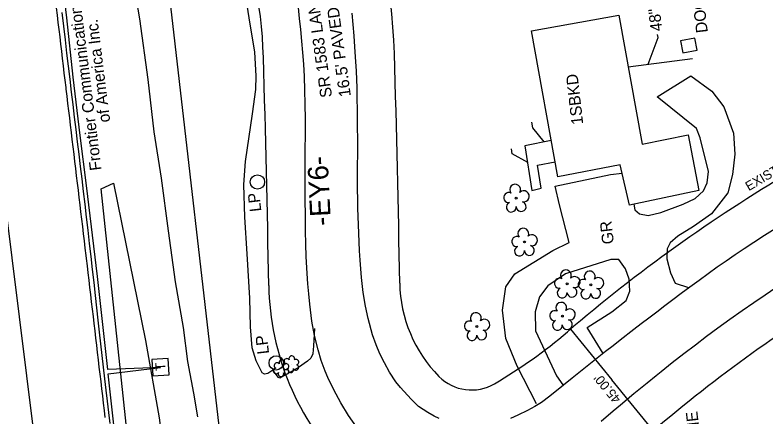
# Model space of a CAD drawing. Extents: x 472260 to 482161, y 489063 to 507124.
# Drawn here: x 478120.1 to 478378, y 497381.3 to 497519.2 of the extents above; entities that cross this region are included whole.
import ezdxf

# ---------------------------------------------------------------- set-up
doc = ezdxf.new("R2010")
doc.units = 0
for name, color, linetype in [('Exist Plan Preparation Watershed Blue', 7, 'Continuous'), ('Exist Structure Minor Drop Inlet Cogo Elevation', 7, 'Continuous'), ('Exist Structure Minor Pipes CMP 15 Inch Cogo Comment', 7, 'Continuous'), ('Exist Structure Minor Pipes CMP 15 Inch Cogo Point CELL', 7, 'Continuous'), ('Prop Drainage Structure Catch Basin Convert From Junction Box Label', 7, 'Continuous'), ('Prop Drainage Structure Drop Inlet Grate 2 Narrow Slots and Sag Grates 840 24 CELL', 7, 'Continuous'), ('Prop Drainage Structure Drop Inlet Grate 2 Narrow Slots and Sag Grates 840 24 Label', 7, 'Continuous'), ('Prop Drainage Structure Drop Inlet Grate 2 Wide Slots and Flat Grates 840 20 Label', 7, 'Continuous'), ('Prop Drainage Structure Drop Inlet Grate 2 Wide Slots and Sag Grates 840 22 Label', 7, 'Continuous'), ('Prop Drainage Structure Outlet Berm Ditch 850 10 CELL', 7, 'Continuous'), ('Prop Drainage Structure Outlet Berm Ditch 850 10 Label', 7, 'Continuous'), ('Prop Drainage Structure Pipe Collar CELL', 7, 'Continuous'), ('Prop Drainage Structure Pipe Collar Label', 7, 'Continuous'), ('Prop Drainage Structure Pipe RCP 18in Class III', 7, 'Continuous'), ('Prop Drainage Structure Pipe RCP 66in Class III Label', 7, 'Continuous'), ('Prop Drainage Structure Pipe RCP 72in Class III', 7, 'Continuous'), ('Prop Drainage Structure Pipe Stub Out CELL', 7, 'Continuous'), ('Prop Drainage Structure Pipe Welded Steel 42in', 7, 'Continuous'), ('Prop Drainage Structure Tops and Inverts LABEL', 7, 'Continuous'), ('Prop Earthen Structure Ditch Flow Line', 7, 'Continuous'), ('Prop Earthen Structure False Sump Label', 7, 'Continuous'), ('Prop Erosion Rip Rap Class B', 7, 'Continuous'), ('Prop Erosion Rip Rap Pad at Outlet CELL', 7, 'Continuous'), ('Prop SS Fill Line', 7, 'Continuous'), ('Scratch_Level_4', 7, 'Continuous')]:
    doc.layers.add(name, color=color, linetype=linetype)

msp = doc.modelspace()

# ---------------------------------------------------------------- linework, layer by layer
at = {"layer": 'Exist Plan Preparation Watershed Blue'}
msp.add_lwpolyline([(478304.26, 497476.19), (478295.26, 497474.27), (478297.62, 497459.04), (478300.85, 497459.8), (478299.55, 497467.66), (478305.58, 497468.87)], dxfattribs=at)
at = {"layer": 'Exist Structure Minor Drop Inlet Cogo Elevation'}
msp.add_line((478344.04, 496042.24), (478169.39, 497559.09), dxfattribs=at)
for centre, radius, start, end in [((478049.09, 497499.96), 201.41, 1.7193, 42.703), ((478049.09, 497499.96), 156.41, 1.7193, 42.7417), ((472276.25, 497326.67), 5976.85, 0.96365, 1.719327), ((472276.25, 497326.67), 5931.85, 0.96365, 1.719327), ((478660.76, 497000.88), 539.39, 120.545, 130.5894), ((478298.83, 497427.98), 91.59, 180.9636, 224.7163), ((478298.83, 497427.98), 46.59, 180.9636, 224.7163), ((478660.76, 497000.88), 494.39, 120.545, 130.5894), ((478198.36, 497540.58), 171.31, 300.3104, 310.5894), ((478276.89, 497406.25), 15.71, 224.7163, 300.3104)]:
    msp.add_arc(centre, radius, start, end, dxfattribs=at)
at = {"layer": 'Exist Structure Minor Pipes CMP 15 Inch Cogo Comment'}
for p in [(478310.9, 497411.38), (478339.39, 497376.55)]:
    msp.add_line(p, (478325.14, 497393.97), dxfattribs=at)
at = {"layer": 'Prop Drainage Structure Catch Basin Convert From Junction Box Label'}
for p, q in [((478128.54, 497360.08), (478111.35, 497498.02)), ((478170.09, 497398.3), (478151.97, 497397.59)), ((478152.13, 497396.04), (478170.09, 497398.3))]:
    msp.add_line(p, q, dxfattribs=at)
for points in [[(478151.97, 497397.59), (478151.77, 497399.63), (478148.48, 497429.53), (478144.63, 497460.75), (478142.47, 497477.82), (478140.06, 497497.85), (478137.95, 497518.18), (478136.03, 497533.62), (478133.37, 497557.17), (478129.16, 497589.17), (478126.48, 497613.21), (478115.94, 497710.98)], [(478163.86, 497293.38), (478161.83, 497310.95), (478158.51, 497339.17), (478155.33, 497367.28), (478152.13, 497396.04)]]:
    msp.add_lwpolyline(points, dxfattribs=at)
at = {"layer": 'Prop Drainage Structure Drop Inlet Grate 2 Narrow Slots and Sag Grates 840 24 CELL'}
msp.add_lwpolyline([(478134.27, 497521.64), (478134.57, 497519.16), (478134.87, 497516.68), (478135.16, 497514.19), (478135.46, 497511.71), (478135.75, 497509.23), (478136.05, 497506.75), (478136.34, 497504.26), (478136.64, 497501.78), (478136.94, 497499.3), (478137.23, 497496.82), (478137.53, 497494.33), (478137.59, 497493.8), (478137.89, 497491.32), (478138.19, 497488.84), (478138.49, 497486.36), (478138.78, 497483.88), (478139.08, 497481.39), (478139.38, 497478.91), (478139.68, 497476.43), (478139.98, 497473.95), (478140.27, 497471.46), (478140.57, 497468.98), (478140.87, 497466.5), (478141.17, 497464.02), (478141.47, 497461.54), (478141.77, 497459.05), (478142.06, 497456.57), (478142.36, 497454.09), (478142.66, 497451.61), (478142.96, 497449.13), (478143.26, 497446.64), (478143.56, 497444.16), (478143.85, 497441.68), (478144.15, 497439.2), (478144.45, 497436.72), (478144.58, 497435.66), (478144.87, 497433.18), (478145.16, 497430.7), (478145.45, 497428.21), (478145.75, 497425.73), (478146.04, 497423.25), (478146.33, 497420.76), (478146.62, 497418.28), (478146.91, 497415.8), (478147.2, 497413.32), (478147.5, 497410.83), (478147.79, 497408.35), (478148.08, 497405.87), (478148.37, 497403.38), (478148.66, 497400.9), (478148.96, 497398.42), (478149.25, 497395.94), (478149.54, 497393.45), (478149.83, 497390.97), (478150.12, 497388.49), (478150.41, 497386), (478150.71, 497383.52), (478151, 497381.04)], dxfattribs=at)
at = {"layer": 'Prop Drainage Structure Drop Inlet Grate 2 Narrow Slots and Sag Grates 840 24 Label'}
msp.add_lwpolyline([(478337.62, 497502.34), (478340.95, 497511.46), (478340.81, 497512.52)], dxfattribs=at)
at = {"layer": 'Prop Drainage Structure Drop Inlet Grate 2 Wide Slots and Flat Grates 840 20 Label'}
for p, q in [((478292.27, 497456.39), (478292.27, 497456.39)), ((478295.08, 497441.32), (478295.08, 497441.32)), ((478309.72, 497426.98), (478309.72, 497426.98)), ((478317.87, 497426.62), (478317.87, 497426.62)), ((478308.1, 497415.88), (478308.1, 497415.88)), ((478278.75, 497412.34), (478278.75, 497412.34))]:
    msp.add_line(p, q, dxfattribs=at)
for centre in [(478292.27, 497456.39), (478295.08, 497441.32), (478309.72, 497426.98), (478317.87, 497426.62), (478308.1, 497415.88), (478278.75, 497412.34)]:
    msp.add_circle(centre, 0.326, dxfattribs=at)
for centre, radius, start, end in [((478291.89, 497459.26), 1.86, 330.1651, 219.7134), ((478294.82, 497456.98), 1.9, 257.1011, 134.1999), ((478289.67, 497456.54), 1.73, 62.6636, 279.3457), ((478290.57, 497453.27), 1.69, 111.5671, 6.231), ((478293.94, 497453.49), 1.7, 181.2822, 74.56), ((478294.69, 497444.19), 1.86, 330.1651, 219.7134), ((478297.63, 497441.91), 1.9, 257.1011, 134.1999), ((478292.47, 497441.47), 1.73, 62.6636, 279.3457), ((478293.37, 497438.2), 1.69, 111.5671, 6.231), ((478296.75, 497438.42), 1.7, 181.2822, 74.56), ((478309.34, 497429.86), 1.86, 330.1651, 219.7134), ((478317.49, 497429.49), 1.86, 330.1651, 219.7134), ((478307.12, 497427.14), 1.73, 62.6636, 279.3457), ((478312.27, 497427.57), 1.9, 257.1011, 134.1999), ((478315.27, 497426.77), 1.73, 62.6636, 279.3457), ((478320.42, 497427.21), 1.9, 257.1011, 134.1999), ((478308.02, 497423.86), 1.69, 111.5671, 6.231), ((478311.39, 497424.08), 1.7, 181.2822, 74.56), ((478319.54, 497423.72), 1.7, 181.2822, 74.56), ((478316.17, 497423.5), 1.69, 111.5671, 6.231), ((478307.72, 497418.75), 1.86, 330.1651, 219.7134), ((478305.49, 497416.03), 1.73, 62.6636, 279.3457), ((478310.65, 497416.47), 1.9, 257.1011, 134.1999), ((478278.37, 497415.21), 1.86, 330.1651, 219.7134), ((478276.15, 497412.49), 1.73, 62.6636, 279.3457), ((478281.3, 497412.93), 1.9, 257.1011, 134.1999), ((478306.4, 497412.76), 1.69, 111.5671, 6.231), ((478309.77, 497412.98), 1.7, 181.2822, 74.56), ((478277.05, 497409.22), 1.69, 111.5671, 6.231), ((478280.42, 497409.44), 1.7, 181.2822, 74.56)]:
    msp.add_arc(centre, radius, start, end, dxfattribs=at)
at = {"layer": 'Prop Drainage Structure Pipe Collar Label'}
for centre in [(478203.37, 497461.91), (478209.82, 497399.83)]:
    msp.add_circle(centre, 2.46, dxfattribs=at)
at = {"layer": 'Prop Drainage Structure Pipe RCP 18in Class III'}
for points in [[(478332.59, 497454.26), (478333, 497452.35), (478334.6, 497451.03), (478337.54, 497450.37), (478341.93, 497451.44), (478349.57, 497454.29), (478353.66, 497456.25), (478356.59, 497458.91), (478357.83, 497461.67), (478358.3, 497465.52), (478355.42, 497477.07), (478354.13, 497480.29), (478340.61, 497491.08), (478352.22, 497498.35), (478359.43, 497493.03), (478363.5, 497487.74), (478366.91, 497478.62), (478367.39, 497471.48), (478366.53, 497464.52), (478364.89, 497458.16), (478359.27, 497450.94), (478353.14, 497446.63), (478347.81, 497443.28), (478345.09, 497441.02), (478344.1, 497439.02), (478343.98, 497435.49), (478345.26, 497430.72), (478346.85, 497427.21), (478351.39, 497425.72)], [(478299.25, 497385.83), (478292.59, 497398.7), (478288.68, 497408.19), (478287.58, 497417.87), (478288.73, 497425.96), (478291.8, 497430.43), (478304.8, 497438.37), (478310.49, 497441.15), (478307.1, 497454.02), (478305.63, 497460.47), (478324.66, 497464.49), (478328.63, 497464.89)], [(478322.11, 497403.06), (478316.61, 497411.96), (478325.07, 497417.31), (478329.97, 497421.23), (478331.23, 497424.47), (478331.06, 497428.54), (478329.8, 497432.12), (478327.49, 497435.36), (478324.71, 497435.29), (478309.14, 497430.42), (478303.16, 497426.26), (478300.28, 497422.55), (478298.73, 497417.4), (478298.92, 497410.79), (478303.64, 497400.59), (478306.14, 497395.37), (478308.25, 497392.27)]]:
    msp.add_lwpolyline(points, dxfattribs=at)
at = {"layer": 'Prop Drainage Structure Pipe RCP 72in Class III'}
msp.add_lwpolyline([(478330.72, 497501.4), (478352.74, 497504.27)], dxfattribs=at)
at = {"layer": 'Prop Drainage Structure Pipe Stub Out CELL'}
for points in [[(478237.45, 497377.87), (478234.65, 497381.78), (478231.97, 497386.09), (478229.57, 497390.55), (478227.57, 497394.84), (478226.68, 497397.05), (478225.31, 497400.71), (478224.2, 497404.32), (478223.01, 497409.21), (478222.11, 497414.13), (478221.37, 497419.96), (478221, 497423.51), (478220.69, 497426.95), (478220.44, 497430.47), (478220.14, 497436.29), (478220, 497440.55), (478219.92, 497445.17), (478219.86, 497450.3), (478219.82, 497455.93), (478219.79, 497461.67), (478219.76, 497467.43), (478219.79, 497472.95), (478219.86, 497478.23), (478219.87, 497483.44), (478219.8, 497488.57), (478219.69, 497493.46), (478219.54, 497498.07), (478219.32, 497502.35), (478219.02, 497506.33), (478218.67, 497510.26), (478218.28, 497514.18), (478217.87, 497518.04), (478217.44, 497521.79)], [(478136.2, 497520.04), (478136.75, 497515.37), (478137.3, 497510.71), (478137.84, 497506.12), (478138.37, 497501.61), (478138.91, 497497.16), (478139.43, 497492.78), (478139.96, 497488.45), (478140.48, 497484.17), (478140.99, 497479.94), (478141.51, 497475.72), (478142.02, 497471.48), (478142.53, 497467.22), (478143.05, 497462.94), (478143.56, 497458.62), (478144.08, 497454.25), (478144.6, 497449.81), (478145.11, 497445.32), (478145.63, 497440.81), (478146.14, 497436.32), (478146.64, 497431.84), (478147.14, 497427.39), (478147.62, 497422.99), (478148.1, 497418.68), (478148.57, 497414.48), (478149.03, 497410.37), (478149.49, 497406.33), (478149.94, 497402.32), (478150.4, 497398.35), (478150.87, 497394.42), (478151.33, 497390.52), (478151.79, 497386.65), (478152.25, 497382.82), (478152.71, 497379.03)], [(478265.77, 497380.79), (478264.09, 497381.59), (478261.93, 497382.8), (478258.72, 497384.88), (478256.15, 497387.4), (478252.56, 497391.4), (478250.93, 497393.38), (478248.74, 497396.6), (478246.97, 497399.81), (478245.45, 497402.96), (478244.12, 497406.06), (478242.91, 497409.43), (478241.38, 497415.11), (478240.48, 497419.3), (478239.7, 497423.97), (478239.1, 497429.17), (478238.66, 497435.07), (478238.46, 497438.27), (478238.28, 497441.41), (478238.05, 497447.17), (478237.9, 497452.89), (478237.82, 497456.03), (478237.78, 497459.33), (478237.76, 497462.81), (478237.79, 497466.51), (478237.83, 497472.45), (478237.82, 497476.6), (478237.79, 497480.7), (478237.73, 497486.69), (478237.67, 497490.61), (478237.6, 497494.24), (478237.4, 497499.96), (478237.07, 497504.85), (478236.85, 497508.24), (478236.58, 497512.07), (478236.25, 497515.96), (478235.87, 497519.84)], [(478381.17, 497445.83), (478377.52, 497443.52), (478373.88, 497441.16), (478370.55, 497438.97), (478367.41, 497436.87), (478364.36, 497434.78), (478361.3, 497432.65), (478358.18, 497430.42), (478355.03, 497428.13), (478351.92, 497425.84), (478348.91, 497423.62), (478346.08, 497421.49), (478343.32, 497419.41), (478340.53, 497417.29), (478337.78, 497415.2), (478335.15, 497413.19), (478332.64, 497411.26), (478327.95, 497407.6), (478325.5, 497405.71), (478322.9, 497403.69), (478320.1, 497401.47), (478317.22, 497399.18), (478314.38, 497396.92), (478311.49, 497394.6), (478308.44, 497392.14), (478303.79, 497388.41), (478300.91, 497386.29), (478298.64, 497384.87), (478296.15, 497383.55), (478292.8, 497381.9), (478290.27, 497380.8)], [(478381.45, 497425.6), (478377.75, 497423.11), (478373.86, 497420.49), (478369.8, 497417.7), (478365.59, 497414.73), (478361.45, 497411.73), (478357.6, 497408.85), (478353.82, 497405.97), (478349.84, 497402.93), (478345.86, 497399.84), (478342.07, 497396.81), (478340.29, 497395.37), (478337.2, 497392.87), (478332.69, 497389.22), (478328.11, 497385.36), (478325.6, 497383.23), (478321.43, 497379.72)]]:
    msp.add_lwpolyline(points, dxfattribs=at)
at = {"layer": 'Prop Drainage Structure Tops and Inverts LABEL'}
msp.add_lwpolyline([(478190.09, 497080.94), (478179.04, 497176.49), (478167.62, 497291.69), (478149.68, 497459.52), (478153.94, 497461.52), (478164.92, 497407.53), (478169.64, 497380.94), (478176.79, 497323.8), (478179.27, 497301.23), (478182, 497244.2), (478186.73, 497178.82), (478185.59, 497158.67), (478193.35, 497075.53), (478190.09, 497080.94)], dxfattribs=at)
at = {"layer": 'Prop Earthen Structure Ditch Flow Line'}
for points in [[(478159.97, 497534.58), (478162.89, 497517.88), (478165.68, 497497.05), (478167.84, 497479.11), (478170.36, 497463.26), (478172.76, 497445.1), (478175.16, 497427.69), (478177.82, 497412.02), (478179.39, 497400.26), (478181.42, 497389.44), (478182.81, 497381.27)], [(478222.93, 497411.63), (478222.68, 497405.72), (478222.36, 497402.94), (478221.66, 497401.5), (478220.57, 497400.41), (478217.52, 497398.26), (478211.09, 497394.64), (478210.56, 497394.8), (478208.65, 497397.29), (478206.98, 497396.24), (478205.78, 497396.02), (478205.05, 497396.39), (478202.91, 497400.49), (478201.59, 497405.04), (478201.01, 497412.18), (478200.79, 497422.07), (478199.82, 497437.28), (478199.08, 497449.8), (478198.76, 497461.08), (478199.22, 497468.97), (478201.66, 497485.25), (478202.82, 497493.61), (478202.97, 497498.33), (478202.44, 497506.49), (478200.53, 497518.23), (478199.48, 497524.91)]]:
    msp.add_lwpolyline(points, dxfattribs=at)
at = {"layer": 'Prop Erosion Rip Rap Class B'}
msp.add_line((478170.09, 497398.3), (478170.09, 497398.3), dxfattribs=at)
msp.add_lwpolyline([(478173.08, 497395.76), (478172.72, 497401.34), (478167.14, 497400.99), (478167.5, 497395.41), (478173.08, 497395.76)], dxfattribs=at)
at = {"layer": 'Prop Erosion Rip Rap Pad at Outlet CELL'}
for p, q in [((478211.59, 497397.78), (478211.59, 497397.78)), ((478214.95, 497399.22), (478214.95, 497399.22))]:
    msp.add_line(p, q, dxfattribs=at)
for centre, radius, start, end in [((478215.18, 497401.26), 0.99, 334.8391, 200.4717), ((478210.1, 497398.9), 0.968, 35.8908, 245.4216), ((478211.81, 497399.82), 0.99, 334.8391, 200.4717), ((478213.15, 497398.52), 0.955, 95.1099, 327.9534), ((478213.47, 497400.35), 0.968, 35.8908, 245.4216), ((478213.26, 497398.65), 0.929, 284.4567, 126.0861), ((478216.63, 497400.09), 0.929, 284.4567, 126.0861), ((478209.79, 497397.07), 0.955, 95.1099, 327.9534), ((478213.22, 497396.85), 0.937, 204.9913, 73.4601), ((478214.83, 497397.54), 0.984, 151.2797, 21.387), ((478216.59, 497398.29), 0.937, 204.9913, 73.4601), ((478211.46, 497396.09), 0.984, 151.2797, 21.387)]:
    msp.add_arc(centre, radius, start, end, dxfattribs=at)
at = {"layer": 'Prop SS Fill Line'}
for points in [[(478297.49, 497513.76), (478327.51, 497519.18), (478335.53, 497474.88), (478351.31, 497478.03), (478354.99, 497458.95), (478331.11, 497453.95), (478327.98, 497467.76), (478306.52, 497463.68)], [(478349.42, 497506.26), (478354.37, 497507.16), (478353.63, 497511.21), (478348.68, 497510.31)]]:
    msp.add_lwpolyline(points, close=True, dxfattribs=at)
at = {"layer": 'Scratch_Level_4'}
for points in [[(478301.87, 497475.73), (478297.91, 497480.44), (478297.64, 497482.48)], [(478296.26, 497468.62), (478290.84, 497471.56), (478290.61, 497473.3)]]:
    msp.add_lwpolyline(points, dxfattribs=at)

# ---------------------------------------------------------------- texts
at = {"layer": 'Exist Structure Minor Pipes CMP 15 Inch Cogo Comment'}
msp.add_text("45.00'", height=3.2, rotation=129.2684, dxfattribs=at).set_placement((478328.41, 497387.56))
at = {"layer": 'Exist Structure Minor Pipes CMP 15 Inch Cogo Point CELL'}
msp.add_text('EXISTING R/W', height=3.2, rotation=30.545, dxfattribs=at).set_placement((478372.13, 497458.72))
at = {"layer": 'Prop Drainage Structure Drop Inlet Grate 2 Wide Slots and Sag Grates 840 22 Label'}
for s, p in [("16.5' PAVED ROADWAY", (478235.49, 497491.4)), ('SR 1583 LANCE RD', (478229.03, 497491.14))]:
    msp.add_text(s, height=4, rotation=97.9227, dxfattribs=at).set_placement(p)
at = {"layer": 'Prop Drainage Structure Outlet Berm Ditch 850 10 CELL'}
for s, p in [('DOGHOUSE', (478358.07, 497513.28)), ('1SBKD', (478315.29, 497481.77)), ('12" STONE', (478357.61, 497355.82))]:
    msp.add_text(s, height=4, rotation=96.5619, dxfattribs=at).set_placement(p)
at = {"layer": 'Prop Drainage Structure Outlet Berm Ditch 850 10 Label'}
msp.add_text('48" CHL', height=4, rotation=96.5619, dxfattribs=at).set_placement((478342.42, 497513.84))
at = {"layer": 'Prop Drainage Structure Pipe Collar CELL'}
msp.add_text('-EY6-', height=7, rotation=92.8682, dxfattribs=at).set_placement((478228.65, 497447.03))
at = {"layer": 'Prop Drainage Structure Pipe RCP 66in Class III Label'}
for p in [(478204.74, 497451.91), (478207.39, 497403.03)]:
    msp.add_text('LP', height=4, rotation=96.5619, dxfattribs=at).set_placement(p)
at = {"layer": 'Prop Drainage Structure Pipe Welded Steel 42in'}
for s, p in [('Frontier Communications', (478149.86, 497466.06)), ('of America Inc.', (478152.85, 497482.57))]:
    msp.add_text(s, height=4, rotation=97.0871, dxfattribs=at).set_placement(p)
at = {"layer": 'Prop Earthen Structure False Sump Label'}
msp.add_text('GR', height=4, rotation=96.5619, dxfattribs=at).set_placement((478325.84, 497440.78))
at = {"layer": 'Prop Erosion Rip Rap Class B'}
msp.add_text('T', height=3.42, rotation=93.6475, dxfattribs=at).set_placement((478171.87, 497397.28))

doc.saveas('drawing.dxf')
